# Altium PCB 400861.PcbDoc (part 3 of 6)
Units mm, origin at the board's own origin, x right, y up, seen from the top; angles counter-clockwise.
Board outline 145 x 63.5 mm, 8 copper layers (Top Side, Mid-Layer 1, Mid-Layer 2, Mid-Layer 3, Mid-Layer 4, Mid-Layer 5, Mid-Layer 6, Bottom Side), stack 1.529 mm thick; 284 components, 233 nets, 1158 pads, 3522 vias.
Unrouted connection lines stored in the file: 1.
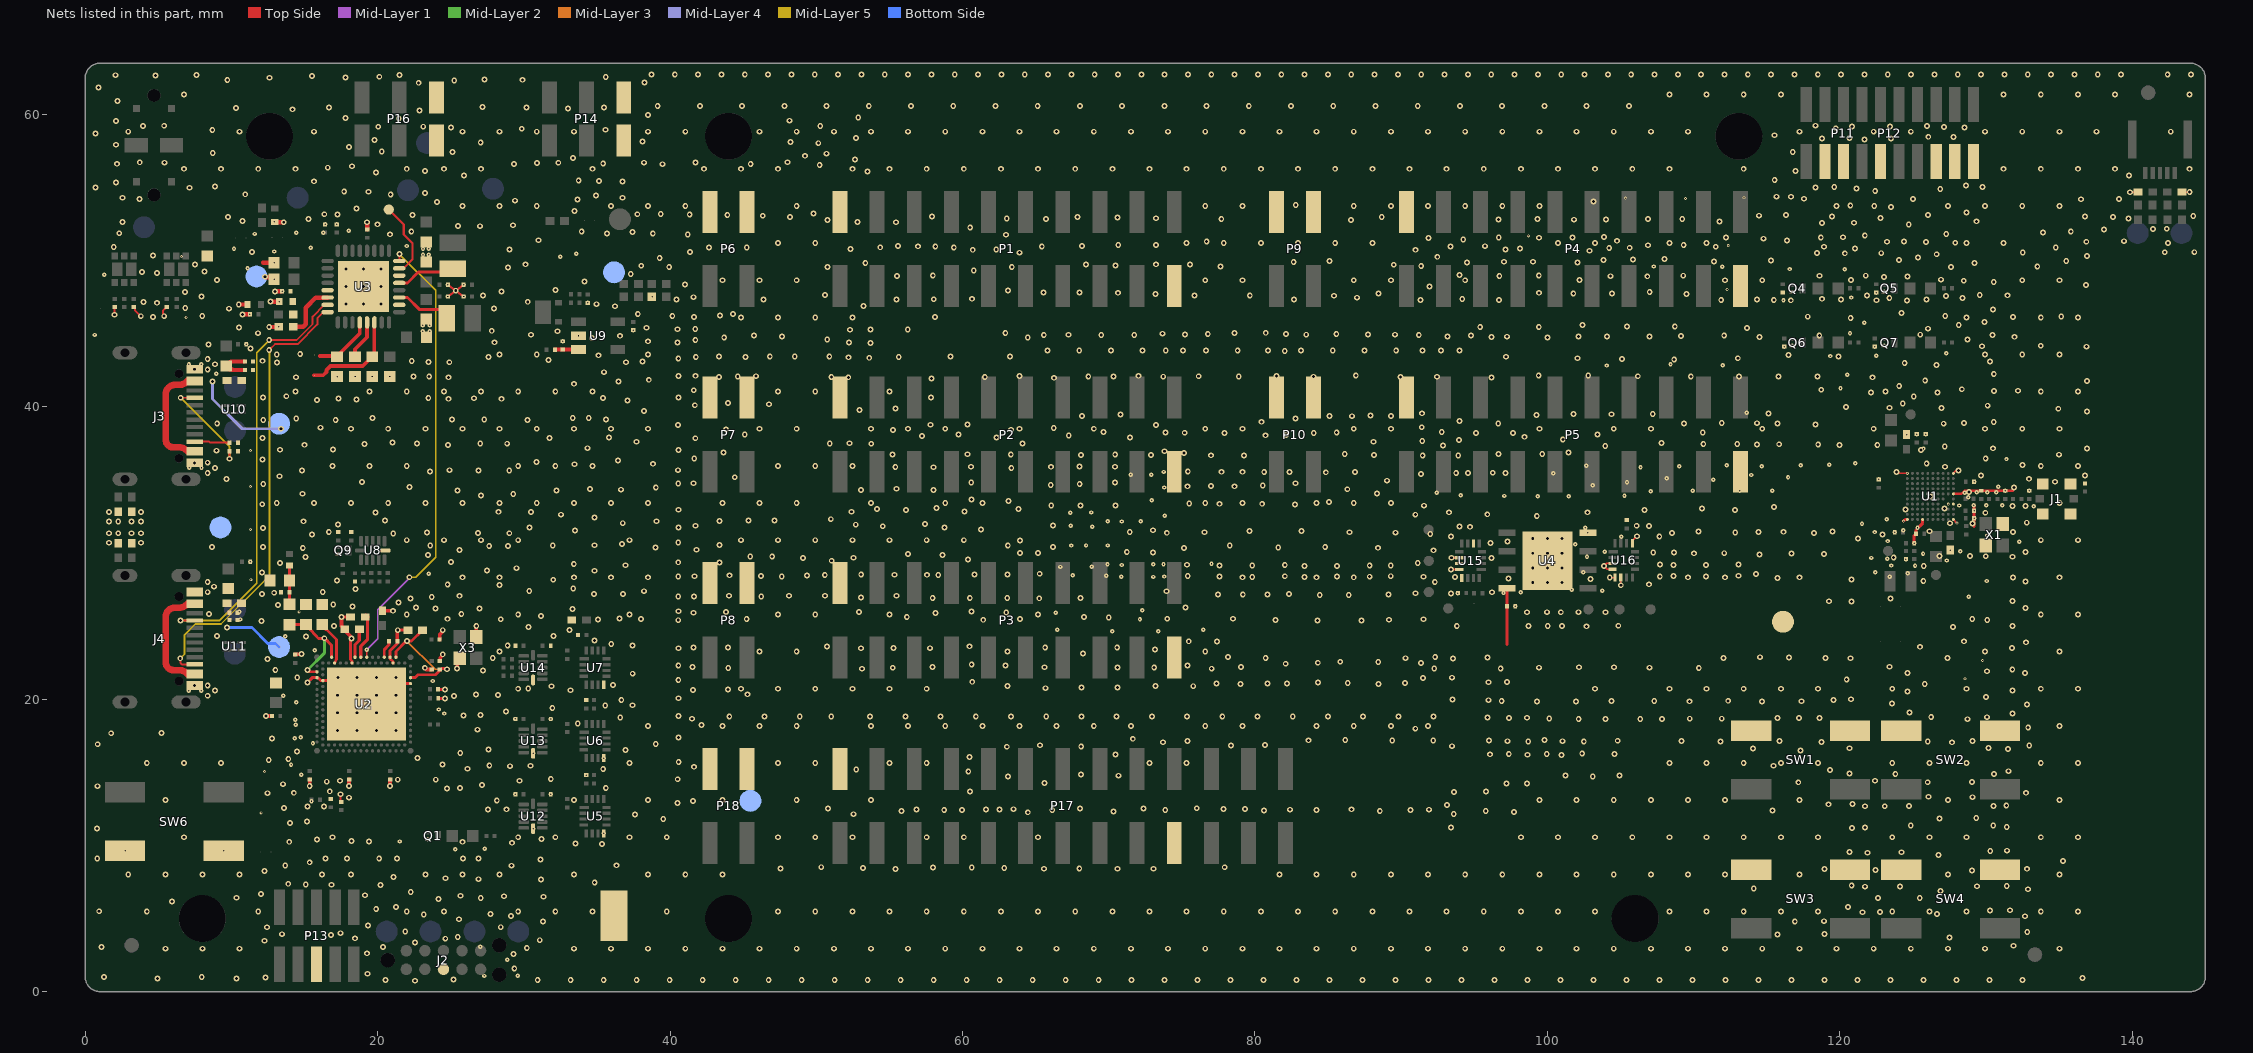
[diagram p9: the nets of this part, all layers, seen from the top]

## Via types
v1: diameter 0.4, hole 0.2, Top Side to Bottom Side, tented both sides, 2426 vias
v2: diameter 0.3, hole 0.1, Top Side to Mid-Layer 1, tented both sides, 299 vias
v3: diameter 0.4, hole 0.2, Mid-Layer 3 to Mid-Layer 4, tented both sides, 197 vias
v4: diameter 0.3, hole 0.1, Mid-Layer 1 to Mid-Layer 2, tented both sides, 197 vias
v5: diameter 0.3, hole 0.1, Mid-Layer 2 to Mid-Layer 3, tented both sides, 91 vias
v6: diameter 0.3, hole 0.1, Mid-Layer 4 to Mid-Layer 5, tented both sides, 81 vias
v7: diameter 0.3, hole 0.1, Mid-Layer 2 to Mid-Layer 3, 71 vias
v8: diameter 0.2, hole 0.1, Top Side to Mid-Layer 1, tented both sides, 64 vias
v9: diameter 0.2, hole 0.1, Mid-Layer 1 to Mid-Layer 2, tented both sides, 41 vias
v10: diameter 0.2, hole 0.1, Mid-Layer 2 to Mid-Layer 3, 19 vias
v11: diameter 0.2, hole 0.1, Mid-Layer 2 to Mid-Layer 3, tented both sides, 14 vias
v12: diameter 0.3, hole 0.1, Mid-Layer 5 to Mid-Layer 6, tented both sides, 12 vias
v13: diameter 0.2, hole 0.1, Mid-Layer 1 to Mid-Layer 2, 4 vias
v14: diameter 0.3, hole 0.1, Top Side to Mid-Layer 1, tented top, 3 vias
v15: diameter 0.2, hole 0.1, Top Side to Mid-Layer 1, tented top, 2 vias
v16: diameter 0.225, hole 0.1, Mid-Layer 1 to Mid-Layer 2, tented both sides, 1 vias

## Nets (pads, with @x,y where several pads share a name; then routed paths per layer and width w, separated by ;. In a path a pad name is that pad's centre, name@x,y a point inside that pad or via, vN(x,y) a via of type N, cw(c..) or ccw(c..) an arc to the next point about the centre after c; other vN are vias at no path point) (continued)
GND: C1.2 C2.2 C3.1 C4.1 C5.2 C6.1 C7.1 C8.1 C9.1 C10.1 C11.1 C12.1 C13.1 C14.1 C15.2 C16.2 C17.2 C18.2 C19.1 C20.2 C21.2 C22.2 C23.2 C24.2 C25.1 C26.2 C27.2 C28.2 C29.2 C30.2 C31.2 C32.1 C33.1 C34.1 C35.1 C36.1 C37.1 C38.1 C39.1 C40.1 C41.1 C42.1 C43.1 C44.1 C45.1 C46.1 C47.1 C48.1 C49.1 C50.1 C51.1 C52.1 C54.2 C55.1 C56.2 C57.1 C58.2 C59.2 C60.2 C61.2 C62.2 C63.1 C64.1 C65.1 C66.1 C67.2 C68.2 C69.1 C70.1 C71.1 C72.1 C73.2 C74.2 C76.1 C77.2 C78.2 C79.2 C80.2 C81.2 C82.2 C83.2 C84.2 C85.2 C86.2 C87.1 C88.1 C89.2 J1.2 J2.3 J3.A1 J3.A12 J4.A1 J4.A12 P1.2 P1.19 P2.2 P2.19 P3.2 P3.19 P4.2 P4.19 P5.2 P5.19 P6.2 P6.4 P7.2 P7.4 P8.2 P8.4 P9.2 P9.4 P10.2 P10.4 P11.3 P11.5 P11.9 P12.3 P12.5 P12.9 P12.15 P12.17 P12.19 P13.5 P14.3 P16.3 P17.2 P17.19 P18.2 P18.4 Q1.2 Q4.2 Q5.2 Q6.2 Q7.2 Q9.2 R2.1 R8.2 R9.2 R10.2 R17.2 R18.2 R20.2 R23.2 R24.2 R29.2 R30.2 R31.2 R32.2 R41.1 R45.1 R46.1 R51.2 R53.1 SW1.1 SW2.1 SW3.1 SW4.1 SW6.1 TP15.1 TP16.1 TP17.1 TP18.1 TP19.1 TP20.1 U1.A1 U1.A7 U1.A10 U1.D1 U1.D2 U1.E5 U1.E6 U1.F1 U1.F5 U1.F6 U1.K1 U1.K10 U2.104 U2.A25 U2.B12 U2.B26 U2.G1 U2.H2 U2.J31 U3.2 U3.6 U3.33 U4.4 U4.9 U5.8 U6.8 U7.8 U8.6 U9.2 U10.5 U10.8 U11.5 U11.8 U12.6 U13.6 U14.6 U15.6 U15.10 U15.11 U15.12 U15.13 U16.3 U16.4 U16.5 U16.6 U16.13 X1.2 X1.4 X3.2 X3.4 | length 45.5
  Top Side w0.1: C71.1@10.424,25.42 10.509,25.458 v2(10.597,25.458) ; v1(104.267,28.32) U16.5@104.623,28.32 ; U16.4@104.448,28.895 104.091,28.895 v1(103.881,29.105) 104.072,29.295 U16.3@104.448,29.295 ; v1(105.023,27.798) U16.6@105.023,28.32 ; U16.13@105.823,30.67 105.823,30.843 v1(106.128,31.147) ; v1(123.874,35.551) ccw(c124.118,35.795) 124.118,35.45 v8(124.62,35.45) ; C7.1@124.529,29.579 v2(124.529,29.583) ; U1.A1@127.77,32.3 v8(128.018,32.052) ; U1.K1@127.77,35.45 127.967,35.647 v1(128.131,35.647) ; v1(139.85,54.679) 140.378,54.679 C57.1@140.4,54.7 ; C56.2@143.4,54.7 143.41,54.69 v1(143.934,54.69)
  Top Side w0.15: v1(2,46.3) 2.01,46.31 2.01,46.811 R24.2@2.02,46.821 ; R23.2@3.32,46.821 3.38,46.761 3.395,46.761 3.395,46.606 v1(3.8,46.2) ; v1(5.4,46.2) 5.4,46.295 5.308,46.387 5.308,46.574 5.555,46.821 R20.2@5.57,46.821 ; v1(17.467,13.504) 17.467,13.018 R10.2@17.5,12.985 ; v2(24.797,47.547) 24.857,47.591 25.822,48.298 v2(25.882,48.342) ; v2(24.797,48.347) 24.857,48.303 25.818,47.592 v2(25.878,47.547) ; v1(93.415,28.883) U15.12@93.975,28.883 ; v1(93.449,29.677) 93.455,29.683 U15.10@93.975,29.683 ; v4(93.875,27.259) C62.2@93.883,27.266
  Top Side w0.152: U1.F1@127.77,34.05 128.32,34.05 128.53,34.261 C3.1@129.688,34.261 129.692,34.264 v2(131.32,34.264) 131.85,34.264
  Top Side w0.2: v1(15.2,21.15) 15.525,21.475 U2.G1@15.85,21.475 U2.G1@15.862,21.475 ; U2.G1@15.901,21.475 16.101,21.275 U2.H2@16.25,21.275 17.05,21.275 17.275,21.5 v1(17.3,21.5) ; v1(18.2,24.15) 18.136,24.086 18.136,22.72 18.25,22.606 U2.B12@18.25,22.475 ; U2.B26@21.05,22.475 21.05,22.575 20.85,22.775 U2.A25@20.85,22.875 20.85,23.325 20.925,23.4 20.925,23.403 21.354,23.832 C31.2@21.354,23.975 ; v1(21.25,21.475) 21.65,21.075 U2.J31@22.25,21.075
  Top Side w0.203: v1(17.525,25.625) 17.53,25.63 C25.1@18.148,25.63 C25.1@18.3,25.63 ; v1(21.375,24.725) C19.1@22.075,24.725 ; R8.2@24.135,20.675 v1(24.6,20.675) ; C22.2@24.143,20.067 24.151,20.059 24.592,20.059 v1(24.6,20.05) ; C5.2@123.761,31.414 v2(123.761,31.419) ; v8(124.372,32.189) 124.484,32.3 U1.A10@124.62,32.3 ; C8.1@125.093,30.677 v2(125.088,30.677) 125.088,31.191 C6.1@125.209,31.312 125.209,31.582 125.67,32.043 U1.A7@125.67,32.3 ; v2(129.176,33.28) 129.183,33.273 v2(129.183,32.889) 129.183,32.376 v2(129.188,32.371) 129.188,31.814
  Top Side w0.225: U2.104@17.85,21.075 U2.104@19.25,19.675 U2.104@19.545,19.675 ; C18.2@20.325,26.025 20.355,26.055 21.053,26.055 v1(21.058,26.05) ; v1(23.225,22.15) v1@23.335,22.04 ; C20.2@24.25,22.61 24.265,22.61 24.288,22.633 24.288,22.839 24.45,23.001 v1(24.45,23.075)
  Top Side w0.25: v1(12.372,18.85) cw(c12.402,18.602) 12.402,18.852 12.759,18.852 C15.2@12.769,18.854 ; C77.2@14.35,23.06 v1(14.8,23.1) ; C32.1@17.75,24.7 v1@18.175,24.275 ; C31.2@21.35,23.975 v1@21.35,24.725 ; v1@23.335,22.04 C23.2@23.7,22.04 ; C24.2@24.238,24.091 24.248,24.101 24.248,24.43 24.377,24.559 24.377,24.585 24.45,24.658 v1(24.45,24.725)
  Top Side w0.254: v1(15.351,14.075) C16.2@15.35,14.515 ; v1(17.525,25.625) 17.525,25.005 C32.1@17.75,24.78 ; v1(18.045,14.075) C17.2@18.046,14.515 ; v1(20.85,14.075) C21.2@20.85,14.515 ; v1(25.438,22.101) 25.438,22.642 X3.4@25.6,22.805 ; v1(26.746,25.009) 26.746,24.259 X3.2@26.75,24.255
  Top Side w0.3: v1(10.5,47) C34.1@11.087,47 ; v1(10.75,46.314) 10.762,46.325 C35.1@11.22,46.325 ; 12.157,49.869 12.167,49.86 12.916,49.86 v2(12.925,49.85) ; v1(12.3,48.9) 12.338,48.862 12.788,48.862 v2(12.925,48.725) ; v1(12.581,45.45) 12.594,45.463 13.219,45.463 v2(13.225,45.469) C39.1@13.231,45.475 ; v1(12.675,47.201) v2(13.263,47.201) ; v1(12.968,47.899) C37.1@13.428,47.899 ; C38.1@12.968,52.638 12.974,52.632 13.569,52.632 v1(13.575,52.625) ; C54.2@19.275,52.135 v1(19.275,52.625)
  other v1: 22.55,0.75 20.525,0.8 30.945,0.804 33.202,0.804 35.459,0.804 37.716,0.804 39.973,0.804 42.229,0.804 44.486,0.804 46.743,0.804 49,0.804 51.257,0.804 53.514,0.804 55.771,0.804 58.028,0.804 60.285,0.804 62.542,0.804 64.799,0.804 67.056,0.804 69.313,0.804 71.57,0.804 73.827,0.804 76.084,0.804 78.341,0.804 80.598,0.804 82.855,0.804 85.112,0.804 87.369,0.804 89.626,0.804 91.883,0.804 94.14,0.804 96.397,0.804 98.654,0.804 100.911,0.804 103.168,0.804 105.425,0.804 107.682,0.804 109.939,0.804 112.196,0.804 114.453,0.804 116.71,0.804 118.967,0.804 121.224,0.804 123.481,0.804 125.737,0.804 127.994,0.804 130.251,0.804 132.508,0.804 25.175,0.825 4.946,0.904 10.334,0.906 136.603,0.939 12.325,0.961 1.288,1.009 7.968,1.008 19.3,1.225 29.345,1.588 29.287,2.585 19.268,2.626 5.48,2.94 8.02,2.94 10.56,2.94 33.42,2.94 35.96,2.94 38.5,2.94 41.04,2.94 43.58,2.94 46.12,2.94 48.66,2.94 51.2,2.94 53.74,2.94 56.28,2.94 58.82,2.94 61.36,2.94 63.9,2.94 66.44,2.94 68.98,2.94 71.52,2.94 74.06,2.94 76.6,2.94 79.14,2.94 81.68,2.94 84.22,2.94 86.76,2.94 89.3,2.94 91.84,2.94 94.38,2.94 96.92,2.94 99.46,2.94 102,2.94 104.54,2.94 107.08,2.94 109.62,2.94 112.16,2.94 114.7,2.94 117.24,2.94 119.78,2.94 122.32,2.94 124.86,2.94 127.4,2.94 129.94,2.94 135.02,2.94 30.201,2.99 1.101,3.062 20.359,3.064 131.872,3.144 22.543,3.372 12.251,3.485 31.083,3.523 24.625,3.625 18.45,3.65 127.5,3.7 25.475,3.75 16.8,3.868 13.463,3.932 15.25,3.932 115.744,3.919 118.964,3.947 17.45,4 132.824,4.086 21.888,4.114 12.424,4.406 28.418,4.411 19.345,4.529 31.319,4.792 116.926,4.79 118.919,4.821 25.553,4.954 132.68,5.16 29.123,5.183 23.153,5.285 27.725,5.325 126.65,5.325 121.548,5.434 122.75,5.45 4.21,5.48 11.83,5.48 21.99,5.48 24.53,5.48 29.61,5.48 32.15,5.48 34.69,5.48 39.77,5.48 47.39,5.48 49.93,5.48 52.47,5.48 55.01,5.48 57.55,5.48 60.09,5.48 62.63,5.48 65.17,5.48 67.71,5.48 70.25,5.48 72.79,5.48 75.33,5.48 77.87,5.48 80.41,5.48 82.95,5.48 85.49,5.48 88.03,5.48 90.57,5.48 93.11,5.48 95.65,5.48 98.19,5.48 100.73,5.48 103.27,5.48 108.35,5.48 110.89,5.48 113.43,5.48 115.97,5.48 118.51,5.48 123.59,5.48 126.13,5.48 128.67,5.48 133.75,5.48 136.29,5.48 0.955,5.5 130.275,5.55 131.638,5.567 19.9,5.65 21.25,5.8 120.568,5.799 5.925,6.175 24.163,6.33 27.05,6.4 10.35,6.425 122.614,6.419 125.472,6.419 31.341,6.492 28.65,6.525 25.675,6.563 19.144,6.598 12.023,6.686 22.265,6.819 126.9,6.875 132.869,7.004 114.117,7.057 121.731,7.18 124.115,7.185 129.389,7.211 131.423,7.226 120.817,7.256 16.839,7.314 20.205,7.305 15.081,7.33 13.885,7.378 34.844,7.466 31.164,7.671 26.901,7.694 24.637,7.758 21.089,7.854 16.184,8.006 2.94,8.02 5.48,8.02 8.02,8.02 10.56,8.02 18.18,8.02 23.26,8.02 25.8,8.02 28.34,8.02 33.42,8.02 38.5,8.02 41.04,8.02 43.58,8.02 81.68,8.02 84.22,8.02 86.76,8.02 89.3,8.02 91.84,8.02 94.38,8.02 96.92,8.02 99.46,8.02 102,8.02 104.54,8.02 107.08,8.02 109.62,8.02 112.16,8.02 117.24,8.02 127.4,8.02 135.02,8.02 12.25,8.25 129.047,8.283 122.451,8.318 55.412,8.4 65.579,8.409 70.611,8.409 73.053,8.409 118.952,8.399 132.809,8.403 47.546,8.42 67.99,8.42 53.193,8.464 62.853,8.453 57.982,8.496 60.633,8.496 77.933,8.509 50.339,8.516 13.681,8.622 29.155,8.618 36.337,8.645 15.35,8.85 135.275,8.95 31.125,9.034 0.819,9.105 16.425,9.12 17.894,9.12 20.104,9.12 21.321,9.12 25.827,9.12 26.886,9.12 126.748,9.348 121.89,9.503 124.212,9.538 120.67,9.559 130.293,9.62 131.442,9.643 35.34,10.103 33.527,10.128 29.192,10.183 13.95,10.25 25.796,10.251 19.4,10.275 18.204,10.301 15.85,10.4 31.194,10.451 6.75,10.56 16.91,10.56 29.61,10.56 32.15,10.56 37.23,10.56 39.77,10.56 47.39,10.56 49.93,10.56 52.47,10.56 57.55,10.56 60.09,10.56 65.17,10.56 98.19,10.56 100.73,10.56 103.27,10.56 105.81,10.56 108.35,10.56 110.89,10.56 113.43,10.56 115.97,10.56 118.51,10.56 123.59,10.56 126.13,10.56 128.67,10.56 133.75,10.56 136.29,10.56 0.809,11.169 120.846,11.198 121.723,11.228 93.401,11.237 131.42,11.253 130.496,11.36 124.853,11.376 14.012,11.538 15.17,11.64 39.533,11.808 126.817,11.84 129.336,11.889 37.594,12.12 52.543,12.139 93.598,12.143 64.466,12.269 97.715,12.285 70.328,12.319 55.82,12.35 88.541,12.347 95.785,12.361 115.4,12.4 58.748,12.424 66.138,12.418 80.619,12.404 84.209,12.418 90.65,12.418 27.535,12.451 56.849,12.452 59.962,12.434 61.612,12.452 73.867,12.432 82.397,12.447 91.895,12.447 28.821,12.475 62.52,12.454 86.615,12.475 63.484,12.482 77.859,12.503 79.317,12.503 50.79,12.518 13.603,12.552 68.035,12.532 72.381,12.532 76.019,12.546 15.209,12.67 16.327,12.669 121.731,12.683 123.078,12.682 124.729,12.688 130.51,12.688 131.392,12.731 93.145,12.775 119.232,12.815 120.882,12.834 40.5,12.899 41.568,13.032 28.149,13.077 5.48,13.1 33.42,13.1 38.5,13.1 43.58,13.1 48.66,13.1 53.74,13.1 99.46,13.1 102,13.1 104.54,13.1 107.08,13.1 109.62,13.1 112.16,13.1 117.24,13.1 127.4,13.1 135.02,13.1 18.049,13.268 129.08,13.301 126.058,13.331 12.475,13.575 14.265,13.603 132.732,13.602 93.623,13.655 60.509,13.687 95.794,13.689 16.724,13.706 24.743,13.907 25.637,13.922 35.604,13.923 0.83,14.055 27.141,14.138 13.522,14.192 97.211,14.249 98.603,14.246 65.597,14.261 117.164,14.319 126.014,14.323 129.05,14.345 16.517,14.363 17.425,14.425 29.702,14.427 122.402,14.426 21.375,14.5 23.975,14.5 40.52,14.53 31.841,14.554 103.103,14.707 63.122,14.725 70.659,14.773 101.246,14.788 104.933,14.788 68.115,14.843 130.557,14.889 123.8,14.9 120.673,14.931 60.398,15.058 131.529,15.081 119.341,15.152 52.733,15.207 35.424,15.229 26.135,15.247 41.634,15.381 29.06,15.423 30.464,15.451 115.466,15.452 27.636,15.476 24.438,15.539 4.21,15.64 6.75,15.64 9.29,15.64 37.23,15.64 47.39,15.64 49.93,15.64 55.01,15.64 57.55,15.64 72.79,15.64 75.33,15.64 108.35,15.64 110.89,15.64 113.43,15.64 115.97,15.64 118.51,15.64 123.59,15.64 126.13,15.64 128.67,15.64 133.75,15.64 136.29,15.64 40.588,15.709 12.55,15.85 13.888,15.911 22.725,15.975 60.481,16.05 98.652,16.203 100.961,16.198 70.456,16.225 96.074,16.235 97.363,16.251 99.957,16.259 104.594,16.266 102.385,16.293 25.65,16.325 14.475,16.436 117.316,16.488 36.948,16.542 27.579,16.555 131.507,16.59 114.061,16.632 120.667,16.652 130.18,16.661 63.03,16.754 68.117,16.763 93.487,16.79 78.352,16.847 132.961,16.842 65.291,16.856 80.69,16.869 0.851,16.921 39.02,16.933 73.71,17.058 127.681,17.057 118.752,17.076 98.692,17.107 102.494,17.104 111.832,17.104 126.017,17.102 97.267,17.131 101.029,17.133 109.182,17.14 115.875,17.134 129.067,17.147 75.394,17.153 89.393,17.17 92.198,17.174 104.811,17.16 83.657,17.194 96.018,17.179 86.178,17.219 99.798,17.204 71.647,17.294 12.774,17.325 40.569,17.392 1.775,17.675 5.225,17.7 17.25,17.875 18.583,17.875 19.917,17.875 21.25,17.875 26.839,17.919 90.97,17.988 132.888,18.073 38.5,18.18 43.58,18.18 46.12,18.18 48.66,18.18 53.74,18.18 56.28,18.18 58.82,18.18 61.36,18.18 63.9,18.18 66.44,18.18 68.98,18.18 71.52,18.18 76.6,18.18 79.14,18.18 84.22,18.18 86.76,18.18 89.3,18.18 91.84,18.18 135.02,18.18 42.15,18.25 33.685,18.337 103.974,18.644 106.352,18.642 128.727,18.637 41.5,18.668 102.144,18.661 107.848,18.652 109.741,18.67 111.927,18.67 100.128,18.684 115.741,18.709 117.208,18.721 118.606,18.709 95.906,18.745 97.37,18.727 98.612,18.738 36.592,18.763 130.063,18.774 126.253,18.786 44.05,18.812 46.458,18.812 48.867,18.812 51.021,18.812 53.683,18.812 56.092,18.812 58.5,18.812 60.909,18.812 63.317,18.812 65.726,18.812 68.134,18.812 70.543,18.812 72.951,18.812 75.359,18.812 77.768,18.812 80.176,18.812 82.585,18.812 84.993,18.812 87.402,18.812 89.81,18.812 92.219,18.812 40.579,18.856 25.881,18.882 27.033,18.929 131.809,19.019 17.25,19.075 18.583,19.075 19.917,19.075 21.25,19.075 124.765,19.099 28.775,19.167 31.944,19.405 35.567,19.577 37.422,19.592 132.799,19.634 123.576,19.719 99.297,19.851 101.948,19.848 109.716,19.86 114.681,19.857 117.378,19.862 96.878,19.883 104.386,19.874 107.309,19.879 112.37,19.894 95.979,19.937 119.576,19.944 36.665,19.958 93.524,19.991 120.761,19.999 40.571,20.072 130.012,20.16 25.228,20.225 8.375,20.243 17.25,20.275 18.583,20.275 19.917,20.275 21.25,20.275 28.229,20.3 26.732,20.335 45.302,20.339 124.622,20.523 8.875,20.593 33.182,20.614 41.575,20.625 131.813,20.607 43.95,20.675 29.61,20.72 44.85,20.72 47.39,20.72 49.93,20.72 52.47,20.72 55.01,20.72 57.55,20.72 103.27,20.72 108.35,20.72 110.89,20.72 113.43,20.72 115.97,20.72 118.51,20.72 123.59,20.72 128.67,20.72 133.75,20.72 136.29,20.72 30.301,20.741 65.688,20.757 70.613,20.793 68.128,20.811 31.891,20.89 63.076,20.908 75.783,20.895 7.485,20.934 73.188,20.916 8.375,20.944 36.102,20.983 79.005,21.035 88.447,21.049 125.813,21.038 77.369,21.076 82.198,21.076 80.859,21.089 90.261,21.104 86.351,21.116 84.308,21.143 95.987,21.164 97.244,21.187 60.665,21.195 40.562,21.308 120.475,21.362 91.492,21.445 18.583,21.475 19.917,21.475 93.486,21.475 14.5,21.5 37.443,21.749 124.637,21.798 132.68,21.806 130.074,21.919 27.193,21.975 13,22 131.802,22.024 53.116,22.086 77.044,22.09 92.264,22.095 96.808,22.11 110.359,22.128 43.976,22.145 55.229,22.155 70.613,22.163 73.11,22.18 99.429,22.16 106.993,22.16 57.941,22.206 65.607,22.19 102.154,22.192 104.557,22.192 41.531,22.208 79.046,22.212 123.398,22.225 62.943,22.3 75.393,22.305 40.562,22.312 60.628,22.389 82.104,22.428 91.35,22.475 84.3,22.498 88.437,22.545 85.834,22.566 12.464,22.762 93.555,22.778 90.297,22.809 119.026,22.815 120.735,22.806 127.363,22.813 27.873,22.821 80.737,22.834 112.058,22.831 95.903,22.851 116.535,22.863 78.153,22.888 92.33,22.884 114.533,22.878 68.231,23.125 28.34,23.26 46.12,23.26 48.66,23.26 76.6,23.26 129.94,23.26 135.02,23.26 63.087,23.277 73.172,23.401 40.567,23.491 53.067,23.489 57.784,23.494 55.286,23.51 131.768,23.516 41.6,23.55 43.954,23.54 65.656,23.543 70.58,23.545 50.732,23.598 125.488,23.588 60.486,23.622 28.893,23.669 37.43,23.689 35.977,23.789 132.739,23.895 77.417,23.952 75.472,23.965 128.488,23.963 34.838,24.025 15.103,24.289 9,24.325 32.029,24.318 33.113,24.726 30.328,24.939 127.749,24.947 102.679,24.991 17.011,25.002 98.711,25.018 100.027,25.014 100.993,25.01 131.809,25.015 104.854,25.03 12.058,25.343 40.56,25.408 130.089,25.416 61.421,25.436 28.416,25.472 35.066,25.46 24.787,25.504 38.007,25.486 45.24,25.483 63.922,25.498 129.063,25.488 36.547,25.513 70.001,25.601 68.316,25.632 56.19,25.637 31.173,25.691 21.99,25.8 29.61,25.8 37.23,25.8 47.39,25.8 49.93,25.8 55.01,25.8 65.17,25.8 133.75,25.8 136.29,25.8 8.475,25.825 25.721,25.837 58.143,25.893 41.612,25.919 62.992,25.933 98.605,25.952 99.982,25.956 100.92,25.953 102.136,25.956 103.979,25.954 43.831,25.969 52.916,25.97 60.606,25.992 40.564,26.018 33.315,26.179 23.953,26.218 26.976,26.206 132.7,26.234 22.623,26.267 18.287,26.334 13.171,26.445 16.96,26.486 21.423,26.609 120.81,26.686 119.255,26.703 131.813,26.723 22.247,26.892 65.247,26.905 123.472,26.888 57.96,26.92 63.059,26.926 68.06,26.926 60.498,26.931 53.05,26.965 23.7,27 40.556,27.022 41.641,27.04 46.235,27.033 25.6,27.075 44.021,27.078 48.127,27.08 50.589,27.08 55.477,27.081 79.172,27.154 80.85,27.154 84.435,27.142 86.415,27.142 89.142,27.166 12.081,27.189 36.786,27.204 82.335,27.19 34.796,27.21 93.401,27.227 90.987,27.253 12.922,27.286 8.375,27.324 16.243,27.336 96.222,27.322 30.365,27.402 38.226,27.391 18.491,27.549 33.377,27.567 8.8,27.7 28.343,27.812 24.789,27.845 106.949,27.862 99.004,27.988 100.004,27.988 101.004,27.988 8.375,28.025 92.302,28.029 132.706,28.055 125.714,28.097 17.216,28.115 32.01,28.175 120.792,28.194 102.963,28.227 97.334,28.26 115.751,28.284 25.8,28.34 28.34,28.34 33.42,28.34 35.96,28.34 38.5,28.34 79.14,28.34 84.22,28.34 86.76,28.34 109.62,28.34 112.16,28.34 117.24,28.34 131.843,28.33 135.02,28.34 79.815,28.369 83.391,28.373 93.673,28.354 40.559,28.385 85.62,28.388 87.85,28.383 91.522,28.382 110.851,28.402 41.658,28.415 47.639,28.408 75.404,28.427 77.586,28.405 82.045,28.415 89.292,28.417 107.693,28.406 46.211,28.437 108.622,28.438 113.081,28.448 44.067,28.478 49.359,28.466 50.583,28.495 58.34,28.491 55.347,28.516 57.564,28.511 60.824,28.522 53.072,28.541 63.07,28.537 114.278,28.571 65.279,28.584 12.1,28.675 34.839,28.792 27.479,28.812 29.507,28.964 99.004,28.988 100.004,28.988 101.004,28.988 83.391,29.115 125.746,29.103 85.62,29.12 77.586,29.147 79.815,29.152 87.85,29.145 89.292,29.16 36.946,29.168 82.045,29.178 108.622,29.18 110.851,29.185 75.347,29.199 107.704,29.209 113.081,29.211 33.414,29.255 13.323,29.33 91.134,29.324 40.558,29.367 43.383,29.358 25.014,29.389 51.053,29.474 60.368,29.556 49.079,29.664 96.186,29.669 52.538,29.679 15.076,29.724 131.821,29.747 45.485,29.756 46.982,29.774 129.984,29.782 23.451,29.866 58.642,29.864 114.507,29.901 118.911,29.927 56.265,29.945 116.695,29.966 65.164,29.992 99.004,29.988 100.004,29.988 101.004,29.988 110.022,29.983 112.1,29.991 63.921,30.013 107.246,30.029 108.67,30.041 132.714,30.066 25.59,30.202 41.8,30.225 14.881,30.355 39.002,30.368 12.153,30.408 8.675,30.425 66.18,30.422 27.627,30.49 28.914,30.49 23.595,30.525 31.974,30.513 34.839,30.535 63.099,30.524 43.376,30.556 36.702,30.625 96.109,30.687 1.628,30.703 3.811,30.703 40.557,30.711 97.274,30.79 63.941,30.852 21.99,30.88 24.53,30.88 27.07,30.88 29.61,30.88 37.23,30.88 44.85,30.88 47.39,30.88 49.93,30.88 52.47,30.88 55.01,30.88 57.55,30.88 60.09,30.88 133.75,30.88 136.29,30.88 99.004,30.988 100.004,30.988 101.004,30.988 121.245,30.998 93.403,31.14 107.657,31.128 15.515,31.268 21.066,31.342 1.631,31.353 2.256,31.353 3.17,31.353 3.813,31.353 26.859,31.368 29.003,31.356 118.232,31.364 108.534,31.377 23.369,31.405 112.851,31.408 16.659,31.432 114.438,31.446 131.85,31.428 116.161,31.453 119.506,31.466 110.343,31.478 33.497,31.54 61.258,31.622 12.15,31.725 30.373,31.746 40.565,31.75 58.766,31.736 94.71,31.796 54.546,31.831 93.983,31.823 106.95,31.843 41.745,31.867 106.112,31.866 66.186,31.896 17.276,31.95 52.697,31.939 57.424,31.996 36.76,32.042 132.787,32.077 1.625,32.15 2.256,32.15 3.17,32.15 3.812,32.152 14.926,32.172 39.06,32.174 43.376,32.188 20.494,32.237 45.369,32.231 47.147,32.231 50.992,32.316 34.839,32.436 32.538,32.623 90.969,32.625 129.955,32.756 19.856,32.778 1.628,32.8 3.811,32.8 28.27,32.821 30.497,32.815 52.404,32.823 60.145,32.842 56.141,32.95 40.571,32.963 54.159,33.02 63.82,33.018 58.213,33.083 131.82,33.211 132.695,33.214 68.075,33.254 70.455,33.254 91.562,33.239 66.072,33.259 82.729,33.315 12.105,33.34 77.585,33.369 80.496,33.369 75.511,33.384 13.1,33.42 15.64,33.42 18.18,33.42 20.72,33.42 23.26,33.42 25.8,33.42 28.34,33.42 30.88,33.42 33.42,33.42 35.96,33.42 38.5,33.42 43.58,33.42 46.12,33.42 48.66,33.42 53.74,33.42 58.82,33.42 61.36,33.42 76.6,33.42 79.14,33.42 84.22,33.42 86.76,33.42 89.3,33.42 135.02,33.42 85.073,33.481 63.141,33.549 60.612,33.663 126.195,33.875 27.06,33.943 14.847,34.058 29.274,34.043 88.339,34.075 25.459,34.268 32.242,34.285 53.048,34.304 58.016,34.312 36.632,34.334 86.319,34.363 34.514,34.392 55.475,34.4 39.023,34.493 131.923,34.475 22.166,34.521 75.391,34.566 78.6,34.566 76.996,34.593 80.533,34.63 66.033,34.659 12.175,34.725 68.016,34.727 40.558,34.757 41.6,34.775 82.775,34.775 60.6,34.825 70.441,34.814 18.932,34.852 134.711,34.875 89.025,34.95 9.65,35.075 132.94,35.079 44.422,35.187 13.274,35.255 136.78,35.308 91.348,35.41 8.375,35.479 93.765,35.487 94.573,35.479 97.147,35.482 96.264,35.491 82.362,35.54 84.848,35.523 77.708,35.558 79.147,35.558 80.633,35.554 86.846,35.555 23.582,35.59 75.41,35.589 28.998,35.64 14.815,35.65 24.912,35.666 26.897,35.65 40.549,35.668 8.875,35.829 63.337,35.824 58.004,35.87 55.403,35.89 60.585,35.904 66.042,35.898 68.007,35.919 70.441,35.904 16.91,35.96 19.45,35.96 21.99,35.96 29.61,35.96 32.15,35.96 34.69,35.96 47.39,35.96 49.93,35.96 52.47,35.96 133.75,35.96 136.29,35.96 132.489,36.018 33.469,36.074 38.82,36.103 7.485,36.17 8.375,36.18 30.857,36.231 36.446,36.335 12.113,36.397 41.655,36.459 129.981,36.46 79.264,36.679 91.475,36.683 93.907,36.672 68.116,36.703 76.999,36.685 88.136,36.698 72.885,36.715 135.001,36.727 55.209,36.743 60.346,36.758 63.305,36.744 70.444,36.735 86.144,36.785 96.665,36.782 99.654,36.777 75.155,36.836 43.652,36.866 101.454,36.868 73.823,36.963 8.975,37 40.567,37.039 13.318,37.068 16.945,37.092 130.474,37.164 136.9,37.16 34.344,37.171 103.96,37.324 92.857,37.355 24.814,37.395 119.991,37.395 14.987,37.405 114.343,37.42 122.569,37.4 115.856,37.444 118.524,37.426 19.107,37.462 110.666,37.448 112.989,37.466 27.016,37.484 28.858,37.479 50.921,37.488 53.758,37.475 64.096,37.491 22.699,37.501 52.264,37.512 107.805,37.52 21.017,37.56 37.701,37.615 88.101,37.614 91.444,37.671 93.95,37.726 101.058,37.757 41.725,37.85 12.125,37.875 31.758,37.863 35.82,37.902 62.328,37.898 71.457,37.901 98.436,37.95 57.22,38.011 67.269,38.034 80.715,38.054 82.119,38.071 45.104,38.104 59.717,38.101 103.422,38.104 75.197,38.231 77.923,38.211 84.024,38.215 95.112,38.214 97.652,38.215 73.891,38.252 85.592,38.237 110.63,38.253 69.645,38.272 92.779,38.284 55.248,38.413 63.314,38.436 43.816,38.457 18.18,38.5 20.72,38.5 23.26,38.5 25.8,38.5 28.34,38.5 30.88,38.5 33.42,38.5 35.96,38.5 38.5,38.5 46.12,38.5 48.66,38.5 53.74,38.5 56.28,38.5 58.82,38.5 63.9,38.5 68.98,38.5 76.6,38.5 79.14,38.5 86.76,38.5 89.3,38.5 99.46,38.5 104.54,38.5 107.08,38.5 114.7,38.5 122.32,38.5 129.94,38.5 132.48,38.5 135.02,38.5 66.24,38.562 16.08,38.574 91.41,38.603 73.238,38.756 40.539,38.768 57.823,38.775 60.351,38.799 118.35,38.796 9.025,38.85 96.644,38.863 109.343,38.864 115.748,38.854 114.335,38.882 111.926,38.896 130.53,38.967 80.452,38.977 93.985,39.02 30.243,39.096 12.175,39.1 17.129,39.105 25.074,39.124 27.288,39.131 35.625,39.125 14.429,39.211 82.786,39.203 19.64,39.228 33.342,39.237 34.438,39.237 68.174,39.374 85.098,39.377 86.645,39.36 89.306,39.377 87.91,39.406 99.247,39.447 70.794,39.472 104.381,39.495 101.796,39.508 107.207,39.518 115.116,39.533 91.422,39.558 38.227,39.704 136.906,39.683 52.95,39.792 134.948,39.872 55.411,39.898 123.411,39.94 120.428,39.992 130.118,40.08 41.69,40.111 46.776,40.179 124.31,40.239 43.953,40.274 37.096,40.424 15.845,40.46 18.564,40.509 24.843,40.549 28.459,40.549 17.324,40.571 26.582,40.589 35.412,40.594 23.463,40.604 40.578,40.634 57.85,40.643 12.15,40.65 125.058,40.698 13.75,40.725 122.129,40.974 126.695,40.985 14.37,41.04 19.45,41.04 21.99,41.04 24.53,41.04 27.07,41.04 29.61,41.04 32.15,41.04 34.69,41.04 47.39,41.04 49.93,41.04 55.01,41.04 123.134,41.041 133.75,41.04 136.29,41.04 130.558,41.094 132.191,41.102 41.618,41.134 118.736,41.171 124.064,41.415 33.431,41.577 36.47,41.737 136.913,41.778 125.844,41.801 38.543,41.848 57.873,41.951 14.408,42.023 24.839,42.021 43.334,42.038 51.026,42.03 52.189,42.019 122.228,42.022 22.459,42.076 23.523,42.086 44.626,42.08 118.487,42.083 40.572,42.106 45.886,42.096 41.747,42.122 130.535,42.254 35.48,42.37 7.485,42.57 8.375,42.56 126.618,42.862 8.875,42.912 124.441,43.007 13.125,43.025 23.473,43.057 24.9,43.05 36.986,43.052 38.113,43.093 130.283,43.104 22.329,43.127 12.125,43.15 31.684,43.193 8.375,43.262 40.563,43.311 53.621,43.354 52.196,43.388 27.575,43.4 45.169,43.411 41.758,43.416 43.343,43.44 48.527,43.435 46.821,43.445 50.889,43.455 35.11,43.524 13.1,43.58 28.34,43.58 30.88,43.58 38.5,43.58 129.94,43.58 132.48,43.58 135.02,43.58 14.7,43.625 82.037,43.829 65.815,43.85 67.983,43.85 70.151,43.85 72.319,43.85 73.902,43.85 75.089,43.861 76.654,43.85 78.822,43.85 80.888,43.85 83.158,43.85 85.325,43.85 87.493,43.85 89.661,43.85 91.468,43.851 92.727,43.864 93.997,43.85 11.3,44 136.878,44.116 129.728,44.147 133.745,44.181 8.425,44.275 53.716,44.375 40.511,44.401 52.229,44.403 27.998,44.414 38.489,44.482 41.725,44.575 50.75,44.6 128.747,44.6 34.669,44.719 43.7,44.75 64.461,44.748 100.02,44.743 96.19,44.785 47.65,44.8 93.167,44.806 97.251,44.799 102.135,44.806 106.98,44.81 114.505,44.789 131.958,44.789 104.077,44.817 109.135,44.837 36.586,44.859 45.75,44.875 94.779,44.884 112.096,44.872 91.209,44.908 30.478,44.93 65.561,44.915 67.255,44.929 69.492,44.923 71.748,44.923 83.508,44.936 89.573,44.936 125.507,44.935 130.456,44.916 75.228,44.941 87.737,44.945 76.777,44.984 82.122,44.984 85.565,44.972 73.69,45.002 11.823,45.038 62.927,45.045 78.604,45.055 80.741,45.064 32.296,45.171 27.8,45.2 52.296,45.274 53.702,45.293 56.254,45.285 40.495,45.306 41.721,45.324 38.388,45.408 10.525,45.425 128.136,45.608 129.898,45.802 44.85,46.12 47.39,46.12 49.93,46.12 52.47,46.12 128.67,46.12 133.75,46.12 136.29,46.12 4.632,46.151 41.645,46.153 58.111,46.156 131.856,46.153 135.15,46.175 8,46.225 40.151,46.224 127.214,46.219 43.409,46.252 37.792,46.341 44.299,46.34 130.481,46.65 9.838,46.714 27.953,46.727 6.839,46.754 36.24,46.88 53.235,46.886 34.955,47.02 17.825,47.025 19.025,47.025 20.225,47.025 4.896,47.117 3.984,47.161 30.267,47.185 124.608,47.274 96.702,47.299 116.651,47.286 122.517,47.292 91.324,47.311 111.89,47.319 115.489,47.315 46.385,47.333 55.484,47.349 82.675,47.332 120.082,47.337 125.941,47.349 40.433,47.353 58.035,47.362 94.18,47.373 114.345,47.353 60.66,47.388 118.784,47.39 123.387,47.439 128.4,47.45 86.978,47.465 41.6,47.5 7.95,47.55 85.4,47.6 127.264,47.581 27.2,47.625 75.875,47.625 79.65,47.625 121.869,47.612 131.474,47.628 50.586,47.654 129.575,47.641 73.2,47.725 109.525,47.725 88.45,47.75 101.775,47.75 104.425,47.75 70.625,47.8 99.425,47.8 65.55,47.825 68,47.825 6.83,47.853 107,47.85 28.477,47.884 25.34,47.944 63.1,47.95 32.151,48.002 17.825,48.225 19.025,48.225 20.225,48.225 91.946,48.231 41.031,48.359 136.838,48.344 34.156,48.57 130.534,48.548 128.478,48.625 43.58,48.66 46.12,48.66 48.66,48.66 76.6,48.66 79.14,48.66 86.76,48.66 89.3,48.66 94.38,48.66 112.16,48.66 114.7,48.66 132.48,48.66 135.02,48.66 9.023,48.687 102.188,48.675 120.78,48.682 126.92,48.697 123.018,48.878 124.642,48.921 55.527,48.948 104.317,48.936 106.838,48.928 57.969,48.977 96.714,48.957 109.295,48.971 118.607,48.967 121.777,48.971 99.415,48.993 93.985,49.019 37.307,49.078 4.901,49.16 3.891,49.215 8.15,49.25 60.771,49.321 17.825,49.425 19.025,49.425 20.225,49.425 28.92,49.525 50.775,49.555 127.604,49.562 39.938,49.568 63.373,49.565 77.65,49.6 133.512,49.588 91.373,49.624 38.029,49.651 70.475,49.675 7.509,49.728 68.45,49.725 75.55,49.725 89.495,49.721 30.1,49.75 73.225,49.75 53.351,49.834 129.223,49.844 94.498,49.868 102.066,49.877 82.652,49.899 97.04,49.925 99.011,49.922 85.103,49.969 135.49,49.973 103.848,50.042 124.05,50.05 105.869,50.072 39.289,50.17 125.362,50.218 92.475,50.261 136.912,50.317 4.637,50.363 126.629,50.439 120.346,50.501 122.837,50.509 63.897,50.544 118.449,50.532 132.515,50.555 142.225,50.574 11.4,50.6 41.35,50.6 144.248,50.578 102.876,50.679 44.19,50.713 29.005,50.75 60.699,50.742 62.31,50.755 90.977,50.741 97.15,50.765 52.343,50.79 98.13,50.822 121.042,50.82 104.23,50.869 105.631,50.88 42.666,50.888 45.242,50.891 59.405,50.899 134.77,50.895 1.95,50.925 54.372,50.911 111.52,50.948 118.925,50.95 56.95,50.981 58.14,50.959 65.425,50.975 93.383,50.978 55.585,50.994 68.175,51 95.728,50.987 106.875,51.05 70.65,51.075 73.225,51.075 109.325,51.075 47.39,51.2 49.93,51.2 75.33,51.2 77.87,51.2 80.41,51.2 82.95,51.2 85.49,51.2 88.03,51.2 100.73,51.2 103.27,51.2 108.35,51.2 110.89,51.2 128.67,51.2 131.21,51.2 142.449,51.213 127.9,51.222 125.906,51.279 76.7,51.3 123.234,51.292 124.383,51.309 136.861,51.29 139.441,51.331 104.764,51.358 116.4,51.375 30.996,51.392 94.25,51.45 114.775,51.5 91.861,51.542 99.429,51.563 96.677,51.591 101.715,51.593 112.221,51.577 118.704,51.592 103.88,51.606 120.231,51.601 121.714,51.725 62.976,51.769 41.21,51.778 20.85,51.8 127.282,51.816 35.678,51.861 38.819,51.866 2.325,51.875 133.892,51.928 37.433,51.954 22.3,52 33.955,52.003 135.802,52.004 138.075,52.121 141.416,52.17 142.366,52.183 60.525,52.275 27.007,52.355 25.5,52.375 29.262,52.42 124.716,52.481 19.979,52.484 118.796,52.584 120.977,52.591 55.45,52.625 2.549,52.65 52.825,52.65 111.775,52.675 10.75,52.7 129.354,52.691 50.764,52.788 86.575,52.775 101.825,52.8 96.65,52.825 104,52.825 15.275,52.85 65.7,52.85 77.7,52.85 99.325,52.85 106.875,52.85 109.225,52.85 63.025,52.875 139.758,52.887 73.225,52.9 122.792,52.922 70.6,52.95 9.775,52.975 48.206,52.984 67.875,52.975 88.675,52.975 138.682,52.986 57.91,53.02 119.475,53.025 136.778,53.021 144.175,53.05 46.335,53.068 114.475,53.075 22.384,53.128 43.914,53.131 116.325,53.125 126.038,53.125 17.25,53.15 41.342,53.154 16.35,53.175 37.758,53.171 39.359,53.194 49.804,53.215 128.679,53.285 33.472,53.396 18.553,53.562 123.503,53.675 25.8,53.74 28.34,53.74 30.88,53.74 35.96,53.74 38.5,53.74 41.04,53.74 48.66,53.74 76.6,53.74 79.14,53.74 86.76,53.74 89.3,53.74 91.84,53.74 94.38,53.74 96.92,53.74 99.46,53.74 119.78,53.74 122.359,53.74 127.4,53.74 129.94,53.74 132.48,53.74 135.02,53.74 120.721,53.77 24.066,54.015 29.4,54.1 33.675,54.175 136.502,54.2 139.107,54.206 3.707,54.218 117.563,54.233 125.018,54.217 2.549,54.3 36.75,54.3 115.673,54.374 116.675,54.37 34.926,54.462 10.945,54.537 20.89,54.528 23.235,54.62 19.372,54.711 17.71,54.729 122.424,54.773 126.875,54.9 121.133,54.944 7.118,54.987 0.7,55 118.335,55.001 119.622,55.045 129.771,55.044 8.862,55.068 128.639,55.132 2.095,55.344 15.657,55.426 36.739,55.424 35.148,55.443 33.75,55.475 115.55,55.525 25.897,55.831 139.775,55.825 19.889,56.018 53.507,56.104 23.244,56.12 116.962,56.141 6.75,56.28 9.29,56.28 11.83,56.28 14.37,56.28 21.99,56.28 24.53,56.28 27.07,56.28 34.69,56.28 42.31,56.28 44.85,56.28 47.39,56.28 52.47,56.28 55.01,56.28 57.55,56.28 60.09,56.28 62.63,56.28 65.17,56.28 67.71,56.28 70.25,56.28 72.79,56.28 75.33,56.28 77.87,56.28 80.41,56.28 82.95,56.28 85.49,56.28 88.03,56.28 90.57,56.28 93.11,56.28 95.65,56.28 98.19,56.28 100.73,56.28 103.27,56.28 105.81,56.28 108.35,56.28 113.43,56.28 131.21,56.28 133.75,56.28 136.29,56.28 138.83,56.28 143.91,56.28 16.587,56.358 18.234,56.457 50.233,56.548 39.477,56.597 2.162,56.623 29.32,56.6 45.513,56.614 35.424,56.646 30.901,56.671 32.354,56.697 5.425,56.7 38.225,56.7 41.749,56.713 3.725,56.725 48.04,56.728 52.636,56.914 33.356,57.022 49.239,57.17 50.689,57.315 8.721,57.37 25.109,57.421 116.782,57.427 20.282,57.473 18.027,57.779 2.1,57.925 50.137,58.033 27.046,58.083 48.238,58.116 38.118,58.143 19.78,58.258 121.69,58.295 118.783,58.354 123.494,58.356 52.705,58.399 120.662,58.394 126.057,58.47 127.778,58.457 115.525,58.575 0.7,58.7 2.94,58.82 10.56,58.82 15.64,58.82 25.8,58.82 28.34,58.82 30.88,58.82 33.42,58.82 38.5,58.82 41.04,58.82 46.12,58.82 48.66,58.82 51.2,58.82 53.74,58.82 56.28,58.82 58.82,58.82 61.36,58.82 63.9,58.82 66.44,58.82 68.98,58.82 71.52,58.82 74.06,58.82 76.6,58.82 79.14,58.82 81.68,58.82 84.22,58.82 86.76,58.82 89.3,58.82 91.84,58.82 94.38,58.82 96.92,58.82 99.46,58.82 102,58.82 104.54,58.82 107.08,58.82 109.62,58.82 117.24,58.82 122.32,58.82 124.86,58.82 129.94,58.82 132.48,58.82 135.02,58.82 137.56,58.82 142.64,58.82 8.689,58.944 35.575,58.95 29.852,59.022 119.723,59.057 25.025,59.1 128.532,59.109 20.04,59.158 23.119,59.161 127.122,59.15 120.838,59.173 123.444,59.165 3.95,59.2 50.268,59.207 125.974,59.21 5.4,59.225 118.344,59.23 2.1,59.55 48.169,59.573 21.439,59.714 17.804,59.748 52.871,59.78 38.5,59.971 22.853,60.276 14.163,60.35 33.028,60.411 10.319,60.437 16.664,60.462 30.175,60.475 35.474,60.478 27.175,60.5 39.153,60.583 42.041,60.583 44.929,60.583 47.817,60.583 50.705,60.583 53.592,60.583 56.48,60.583 59.368,60.583 62.256,60.583 65.144,60.583 68.031,60.583 70.919,60.583 73.807,60.583 76.695,60.583 79.583,60.583 82.47,60.583 85.358,60.583 88.246,60.583 91.134,60.583 94.022,60.583 96.91,60.583 99.797,60.583 102.685,60.583 105.573,60.583 2.215,60.924 6.75,61.36 108.35,61.36 110.89,61.36 113.43,61.36 115.97,61.36 131.21,61.36 133.75,61.36 136.29,61.36 138.83,61.36 143.91,61.36 0.913,61.848 22.806,62.164 38.261,62.183 25.238,62.329 9.717,62.366 27.318,62.382 29.915,62.369 12.612,62.506 17.792,62.522 35.6,62.55 20.112,62.576 15.503,62.636 2.071,62.683 4.809,62.672 7.615,62.694 21.5,62.701 38.728,62.719 40.324,62.719 41.919,62.719 43.515,62.719 45.11,62.719 46.705,62.719 48.301,62.719 49.896,62.719 51.491,62.719 53.087,62.719 54.682,62.719 56.278,62.719 57.873,62.719 59.468,62.719 61.064,62.719 62.659,62.719 64.255,62.719 65.85,62.719 67.445,62.719 69.041,62.719 70.636,62.719 72.232,62.719 73.827,62.719 75.422,62.719 77.018,62.719 78.613,62.719 80.209,62.719 81.804,62.719 83.399,62.719 84.995,62.719 86.59,62.719 88.185,62.719 89.781,62.719 91.376,62.719 92.972,62.719 94.567,62.719 96.162,62.719 97.758,62.719 99.353,62.719 100.949,62.719 102.544,62.719 104.139,62.719 105.735,62.719 107.33,62.719 108.926,62.719 110.521,62.719 112.116,62.719 113.712,62.719 115.307,62.719 116.902,62.719 118.498,62.719 120.093,62.719 121.689,62.719 123.284,62.719 124.879,62.719 126.475,62.719 128.07,62.719 129.666,62.719 131.261,62.719 132.856,62.719 134.452,62.719 136.047,62.719 137.643,62.719 139.238,62.719 142.429,62.719 144.024,62.719
  other v2: 2.724,9.637 9.474,9.637 25.3,9.75 27.325,9.775 21.5,10.275 23.424,10.425 35.472,10.831 30.631,11.156 29.42,13.515 31.841,13.511 14.775,14.825 34.272,14.817 35.472,15.971 30.631,16.296 14.325,17.325 14.4,18.25 29.421,18.654 31.841,18.651 24.175,19.3 7.08,20.588 7.925,20.588 23.775,21.25 13.675,24.3 10.526,25.98 97.806,26.364 93.875,27.259 125.147,29.124 123.525,29.146 11.285,29.4 127.323,29.492 125.694,29.939 128.243,30.122 127.552,30.202 123.28,30.822 102.776,31.393 122.388,31.437 123.202,32.309 133.264,33.193 128.179,33.252 130.03,33.277 131.1,33.268 128.556,34.124 129.371,34.166 130.09,34.156 130.703,34.162 132.962,34.264 129.188,34.877 122.678,35.061 7.125,35.829 7.95,35.829 125.727,37.149 124.568,38.101 125.874,38.136 17.225,42.05 18.451,42.077 19.625,42.077 20.825,42.077 8.95,42.26 104.05,42.825 112,42.85 7.093,42.925 7.925,42.925 108.425,42.925 119.35,43.475 122.5,43.5 127.275,43.675 116.2,44.115 122.4,44.115 116.75,44.175 123.05,44.175 11.01,44.275 32.667,44.486 33.735,44.866 0.661,44.916 120.7,45.025 23.074,45.177 23.574,45.177 37.479,45.247 23.074,45.567 23.574,45.567 121.675,45.75 11.265,46.325 34.361,47.117 116.15,47.3 120.775,47.475 38.768,47.541 122.5,47.815 123.05,47.875 13.465,47.899 1.296,49.033 120.35,49.4 116.575,49.425 11.1,49.475 111.975,49.575 107.275,49.6 32.501,50.254 23.1,50.4 23.5,50.4 33.575,50.475 12.925,50.625 23.1,50.8 23.5,50.8 15.425,50.875 22,51 16.402,52.485 17.2,52.485 12.929,52.65
  other v3: 93.808,25.005 84.269,25.389 87.298,25.389 81.411,25.419 89.165,25.438 91.539,25.473 74.005,25.507 78.498,25.507 75.241,26.274 77.48,27.167 73.958,27.386 123.687,29.699 126.817,29.808 128.905,29.808 73.03,30.028 71.238,30.079 92.211,30.188 75.148,30.344 88.422,30.36 81.597,30.391 84.806,30.423 78.278,30.517 122.913,31.27 91.991,31.315 73.974,31.385 89.612,31.393 76.556,31.425 86.465,31.425 71.439,31.442 126.14,31.491 79.625,31.518 83.178,31.518 73.029,31.56 129.089,32.014 127.54,32.036 99.278,32.541 95.894,32.65 93.274,32.786 102.745,32.786 106.648,32.95 112.843,32.95 124.498,32.99 127.154,33.042 110.578,33.059 115.491,33.141 128.83,34.166 129.667,35.312 127.194,35.901 125.946,36.116 125.552,37.055 127.18,37.284 127.108,38.848 128.502,38.903 126.957,39.923 128.347,41.202 66.255,41.987 96.192,42.014 61.526,42.047 73.729,42.061 84.015,42.061 89.957,42.044 92.442,42.059 115.807,42.067 68.604,42.077 70.336,42.077 76.153,42.091 78.894,42.076 106.186,42.091 109.813,42.082 113.111,42.082 63.891,42.107 81.485,42.106 72.038,42.122 86.9,42.135 99.409,42.151 102.798,42.151 108.677,43.247 105.104,43.267 102.063,43.326 113.027,43.326 55.638,43.412 97.169,43.428 59.177,43.442 63.243,43.442 119.909,43.447 116.502,43.551 118.602,44.887 126.042,45.347 113.661,45.398 99.417,45.47 95.406,45.473 108.717,45.485 105.455,45.5 102.414,45.588 120.748,46.067 117.808,46.165 124.233,46.408 111.395,49.948 115.307,50.011 108.006,50.122 82.794,53.796 103.169,54.035
  other v4: 27.3,1.075 29.575,1.1 28.85,2.175 27.025,3.075 15.475,13.025 14.075,15.525 15.575,17 14.75,17.4 14.375,18.6 24.55,19.025 14.425,19.8 13.55,20.25 15.7,23.35 123.418,28.387 23.5,28.575 124.66,28.628 122.418,28.683 77.029,29.275 124.529,29.583 123.239,29.616 122.158,29.665 125.088,30.677 132.266,30.777 130.091,31.202 124.342,31.559 125.318,31.735 121.521,32.003 123.202,32.309 128.776,33.814 130.09,34.156 130.828,34.532 131.4,36.431 124.568,38.101 113.637,39.588 120.051,41.283 120.5,42.2 10.175,50.8 11.6,51.825 14.425,51.9 16.275,51.9 18.025,52.05
  other v7: 70.249,24.658 73.382,24.651 66.488,24.763 76.478,24.757 72.137,25.477 66.382,25.929 72.283,26.095 128.834,27.015 97.001,27.267 98.192,27.311 103.767,27.409 101.678,27.481 130.052,28.088 70.862,28.377 73.056,28.364 73.803,28.395 69.829,28.441 67.55,28.493 102.463,28.695 66.698,29.048 68.841,29.061 70.887,29.183 69.919,29.222 73.038,29.225 73.748,29.228 102.713,29.749 103.919,30.099 67.433,30.514 68.448,30.52 69.943,30.52 101.901,30.593 105.065,31.114 102.591,31.739 68.887,31.794 67.408,31.855 70.893,32.159 69.925,32.169 72.186,32.165 73.822,32.556 67.373,32.759 68.808,32.778 72.955,33.62 99.34,33.884 101.459,33.884 97.047,33.904 105.274,33.923 94.079,33.962 92.441,34.135 107.07,34.22 109.954,34.251 113.153,34.267 115.391,34.251 73.805,34.484 103.099,34.645 105.447,34.85 111.357,35.023 108.173,35.118 116.463,35.181 71.517,35.356 72.906,35.354 113.941,35.339 100.409,35.447 73.763,35.548 106.374,35.872 109.031,35.927 114.676,35.94 102.659,35.983 112.282,36.002 117.342,36.005 119.284,36.032 121.063,36.138
  other v8: 127.42,33.35
  other v10: 12.025,12.225 12.272,15.05 128.566,21.402 129.766,22.652 14.625,25.975 11.325,28.175 11.3,31.625 11.3,34.55 11.3,37 6.9,46.125 112.3,48.025 6.575,50.275 112.375,51.025 98.709,51.7 109.45,54.25 105.35,54.275 113.45,54.3
  other v14: 125.274,38.136
LDO1: C33.2 U3.29 | length 2.7
  Top Side w0.254: C33.2@18.451,43.4 18.451,43.94 19.275,44.764 U3.29@19.275,45.775
LDO1_CTRL: TP35.1 U3.7 | length 5.2
  Top Side w0.15: TP35.1@20.761,53.497 21.784,52.474 21.784,51.79 22.373,51.201 22.373,50.074 21.775,49.475 U3.7@21.475,49.475
LED_PWR_CTRL: U2.A17 U3.8 | length 31.3
  Top Side w0.125: U2.A17@19.25,22.875 v2(19.25,23.375) ; U3.8@21.475,49.975 21.5,50 21.482,50.018 v1(21.482,50.456)
  Mid-Layer 1 w0.125: v2(19.25,23.375) 20,24.125 20,26.127 22.163,28.289 v1(22.163,28.345)
  Mid-Layer 5 w0.125: v1(22.163,28.345) 22.598,28.345 23.971,29.717 23.971,30.357
  Mid-Layer 5 w0.127: v1(21.482,50.456) 21.482,50.451 23.971,47.963 23.971,30.357
NetC19_2: C19.2 C20.1 U2.A27 U2.G31 | length 8.9
  Top Side w0.2: U2.A27@21.25,22.875 21.25,23.268 v1@21.957,23.975 ; v1(22,23.975) 22.314,23.975 23.025,24.686 C19.2@23.025,24.725 ; U2.G31@22.25,21.475 22.55,21.475 22.75,21.675 23.925,21.675 ; 23.95,21.675 24.365,22.09 v1@24.59,22.09
  Mid-Layer 3 w0.1: v1(22,23.975) 23.925,22.05 v1(24.75,22.05)
NetC25_2: C25.2 U2.A15 | length 3.1
  Top Side w0.225: U2.A15@18.85,22.875 18.85,23.612 19.3,24.062 C25.2@19.3,25.63
  Top Side w0.25: C25.2@19.177,25.753 C25.2@19.3,25.63
NetC27_1: C27.1 C28.1 FB5.1 R11.1 | length 2.6
  Top Side w0.203: R11.1@13.972,26.5 FB5.1@13.972,29.139
NetC29_1: C29.1 R11.2 U2.A5 U2.E1 | length 7.7
  Top Side w0.158: v1(15.2,22) 15.325,21.875 U2.E1@15.85,21.875
  Top Side w0.2: R11.2@13.972,25.1 13.997,25.125 C29.1@15.1,25.125 ; C29.1@15.1,25.125 15.349,24.85 ccw(c15.546,24.887) 15.4,24.75 15.766,24.359 ccw(c15.912,24.496) 15.77,24.355 15.771,24.354 15.961,24.164 16.339,24.164 v1(16.35,24.175) 16.375,24.175 16.85,23.7 U2.A5@16.85,22.875
  Mid-Layer 2 w0.2: v1(15.2,22) 16.35,23.15 v1(16.35,24.175)
NetC30_1: C30.1 U2.B6 | length 3.1
  Top Side w0.187: C30.1@16.2,25.125 16.389,24.844 ccw(c16.537,24.957) 16.405,24.825 16.456,24.774 16.501,24.774 17.181,24.094 17.181,22.749 ; U2.B6@17.05,22.475 17.181,22.745
NetC31_1: C31.1 U2.A23 | length 1.2
  Top Side w0.2: U2.A23@20.45,22.875 20.45,23.387 20.784,23.721 C31.1@20.784,23.975
NetC32_2: C32.2 U2.A13 | length 2
  Top Side w0.225: U2.A13@18.45,22.875 18.45,23.72 18.75,24.02 C32.2@18.75,24.78
NetC36_2: C36.2 C37.2 R14.2 U3.21
NetC39_2: C39.2 U3.22 | length 4.1
  Top Side w0.305: C39.2@14.231,45.475 14.904,45.475 ; U3.22@16.575,47.475 15.77,47.475 15.082,46.788 15.082,45.654 ; 14.904,45.475 15.082,45.654 ; 14.904,45.475 15.082,45.654
NetC50_2: C50.2 SB29.2 SB30.2 U3.30 | length 7
  Top Side w0.254: 15.647,42.161 16.276,42.161 16.5,42.385 16.5,42.512 16.776,42.787 18.985,42.787 C50.2@19.625,43.427 19.775,43.577 U3.30@19.775,45.775
NetC51_2: C51.2 SB27.2 SB28.2 U3.28 | length 4.2
  Top Side w0.254: 16.044,43.477 17.175,43.477 17.178,43.474 C51.2@17.225,43.427 ; C51.2@17.225,43.461 18.775,45.011 U3.28@18.775,45.775
NetC58_1: C58.1 SB23.2 SB24.2 U4.8 | length 3.8
  Top Side w0.203: U4.8@97.234,27.583 97.234,23.745 SB24.2@97.241,23.738
NetC60_1: C60.1 R55.2 U9.3 | length 1.6
  Top Side w0.254: R55.2@32.117,43.916 U9.3@33.733,43.916
NetC64_2: C64.2 C65.2 C66.2 FB3.1 J3.A4 J3.A9 TP21.1 U10.1 | length 17.4
  Top Side w0.3: C66.2@10.915,42.52 10.06,42.52 10.009,42.572 9.86,42.572 FB3.1@9.635,42.797 9.66,42.797 9.963,43.1 C65.2@10.915,43.1
  Top Side w0.45: J3.A9@6.989,36.965 J3.A9@7.485,36.965 ; J3.A4@6.989,41.765 J3.A4@7.485,41.765 ; J3.A9@6.989,36.965 ccw(c6.415,36.475) 6.396,37.23 6.035,37.23 cw(c6.035,37.765) 5.5,37.765 5.5,40.865 cw(c6.135,40.865) 6.135,41.501 6.396,41.501 ccw(c6.415,42.255) J3.A4@6.989,41.765
  Mid-Layer 4 w0.2: v1(8.7,41.729) 8.7,40.536 10.736,38.5 v1(13.4,38.5)
NetC70_2: C70.2 C71.2 C72.2 FB4.1 J4.A4 J4.A9 TP24.1 U11.1 | length 12
  Top Side w0.45: J4.A9@6.989,21.729 J4.A9@7.485,21.729 ; J4.A4@6.989,26.529 J4.A4@7.485,26.529 ; J4.A9@6.989,21.729 ccw(c6.415,21.239) 6.396,21.994 6.035,21.994 cw(c6.035,22.529) 5.5,22.529 5.5,25.629 cw(c6.135,25.629) 6.135,26.264 6.396,26.264 ccw(c6.415,27.019) J4.A4@6.989,26.529
  Bottom Side w0.2: v1(9.7,24.9) 11.4,24.9 12.48,23.82 13.01,23.82 TP24.1@13.259,23.572
NetJ3_A5: J3.A5 R46.2 | length 7
  Top Side w0.125: v1(6.527,40.62) J3.A5@7.485,40.62 J3.A5@7.487,40.62 ; R46.2@9.865,36.97 9.87,36.965 9.87,36.455 v1(9.875,36.45)
  Mid-Layer 5 w0.125: v1(6.527,40.62) 9.875,37.272 v1(9.875,36.45)
NetJ3_B5: J3.B5 R45.2 | length 2.4
  Top Side w0.125: J3.B5@7.485,37.62 7.49,37.625 8.475,37.625 8.55,37.55 R45.2@9.865,37.55
NetJ4_A5: J4.A5 U3.23 | length 29.5
  Top Side w0.125: v1(6.525,25.384) J4.A5@7.485,25.384 ; v1(12.581,44.564) 14.449,44.564 15.55,45.665 15.55,46.173 16.353,46.975 U3.23@16.575,46.975
  Mid-Layer 5 w0.125: v1(6.525,25.384) 9.174,25.384 11.725,27.935 11.725,43.708 v1(12.581,44.564)
NetJ4_B5: J4.B5 U3.24 | length 31.3
  Top Side w0.125: v1(6.5,22.8) 6.519,22.502 ccw(c6.644,22.511) 6.644,22.386 6.978,22.386 J4.B5@7.485,22.384 ; v1(12.581,43.898) 12.978,44.294 14.527,44.294 15.875,45.642 15.875,46.062 16.289,46.475 U3.24@16.575,46.475
  Mid-Layer 5 w0.125: v1(6.5,22.8) 6.797,23.098 6.797,24.411 7.536,25.149 9.286,25.149 12.6,28.463 12.6,43.879 v1(12.581,43.898)
NetL5_2: L5.2 U3.3 | length 3.9
  Top Side w0.2: U3.3@21.475,47.475 22.038,47.475 22.841,46.672 24.262,46.672 24.727,46.207 L5.2@24.727,46.047
NetL6_2: L6.2 U3.5 | length 5.1
  Top Side w0.2: U3.5@21.475,48.475 22.038,48.475 ; L6.2@25.125,49.44 24.902,49.217 22.78,49.217 ; 22.038,48.475 22.78,49.217 ; 22.038,48.475 22.78,49.217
